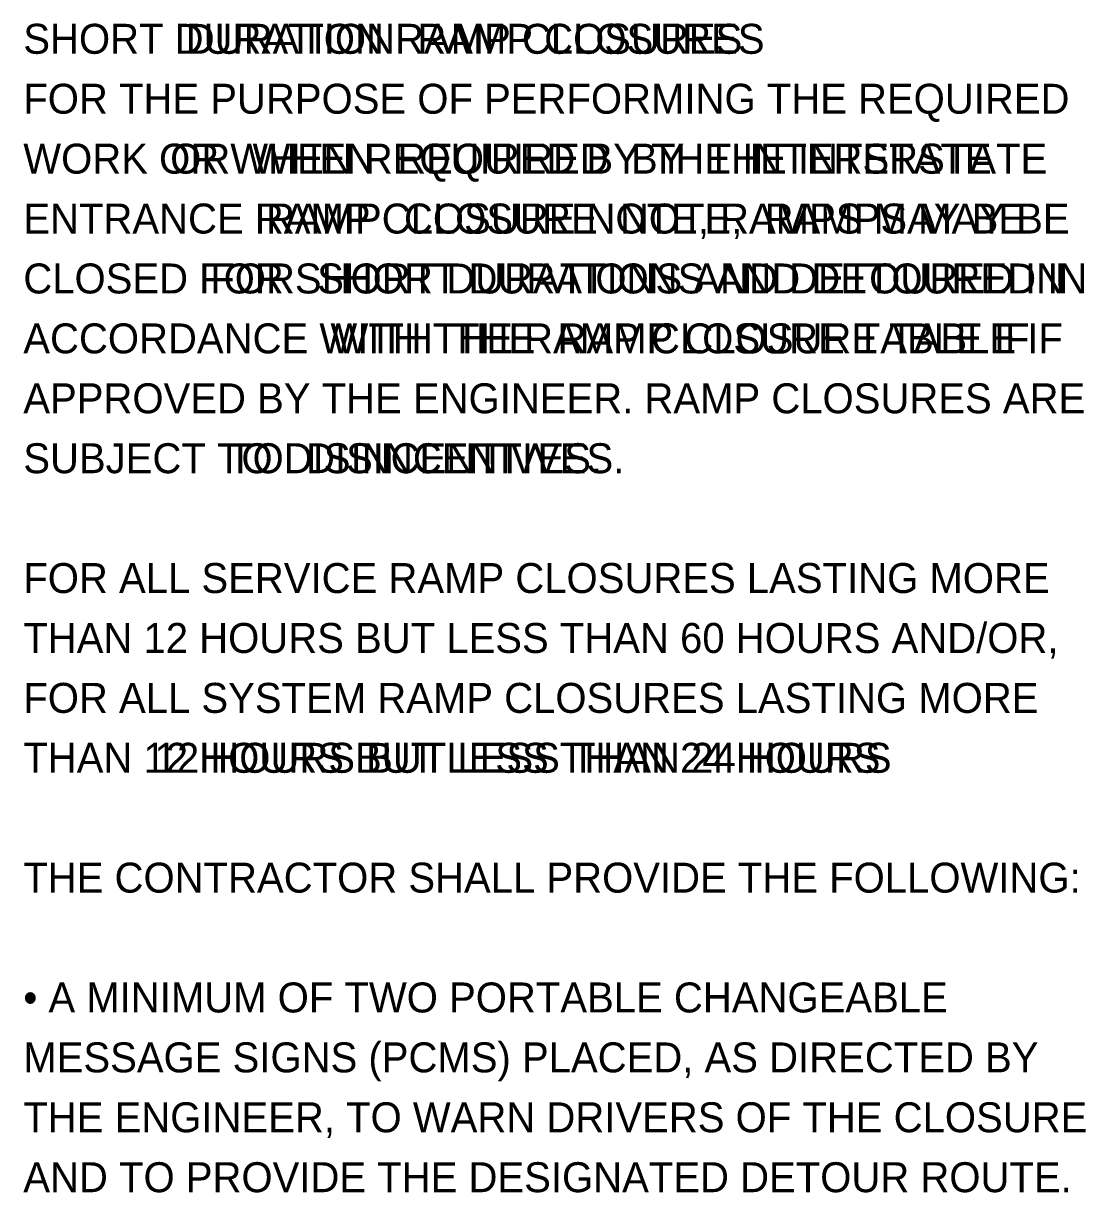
# Model space of a CAD drawing. Extents: x 0 to 37668, y -5 to 18949.
# Drawn here: x 0 to 4.96, y -5.46 to 0 of the extents above; entities that cross this region are included whole.
import ezdxf

# ---------------------------------------------------------------- set-up
doc = ezdxf.new("R2010")
doc.units = 0
doc.layers.add('SH_Text', color=7, linetype='Continuous')

msp = doc.modelspace()

# ---------------------------------------------------------------- texts
at = {"layer": 'SH_Text'}
for s, p in [('SHORT  DURATION  RAMP CLOSURES', (0, -0.14)), ('SHORT  DURATION  RAMP CLOSURES', (0, -0.14)), ('SHORT DURATION RAMP CLOSURES', (0, -0.14)), ('FOR THE PURPOSE OF PERFORMING THE REQUIRED', (0, -0.42)), ('FOR THE PURPOSE OF PERFORMING THE REQUIRED', (0, -0.42)), ('FOR THE PURPOSE OF PERFORMING THE REQUIRED', (0, -0.42)), ('WORK  OR  WHEN  REQUIRED  BY  THE INTERSTATE', (0, -0.7)), ('WORK  OR  WHEN  REQUIRED  BY  THE INTERSTATE', (0, -0.7)), ('WORK OR WHEN REQUIRED BY THE INTERSTATE', (0, -0.7)), ('ENTRANCE  RAMP  CLOSURE  NOTE,  RAMPS MAY BE', (0, -0.98)), ('ENTRANCE  RAMP  CLOSURE  NOTE,  RAMPS MAY BE', (0, -0.98)), ('ENTRANCE RAMP CLOSURE NOTE, RAMPS MAY BE', (0, -0.98)), ('CLOSED  FOR  SHORT DURATIONS AND DETOURED IN', (0, -1.26)), ('CLOSED  FOR  SHORT DURATIONS AND DETOURED IN', (0, -1.26)), ('CLOSED FOR SHORT DURATIONS AND DETOURED IN', (0, -1.26)), ('ACCORDANCE  WITH  THE  RAMP CLOSURE TABLE IF', (0, -1.54)), ('ACCORDANCE  WITH  THE  RAMP CLOSURE TABLE IF', (0, -1.54)), ('ACCORDANCE WITH THE RAMP CLOSURE TABLE IF', (0, -1.54)), ('APPROVED BY THE ENGINEER. RAMP CLOSURES ARE', (0, -1.82)), ('APPROVED BY THE ENGINEER. RAMP CLOSURES ARE', (0, -1.82)), ('APPROVED BY THE ENGINEER. RAMP CLOSURES ARE', (0, -1.82)), ('SUBJECT  TO  DISINCENTIVES.', (0, -2.1)), ('SUBJECT  TO  DISINCENTIVES.', (0, -2.1)), ('SUBJECT TO DISINCENTIVES.', (0, -2.1)), ('FOR ALL SERVICE RAMP CLOSURES LASTING MORE', (0, -2.66)), ('FOR ALL SERVICE RAMP CLOSURES LASTING MORE', (0, -2.66)), ('FOR ALL SERVICE RAMP CLOSURES LASTING MORE', (0, -2.66)), ('THAN 12 HOURS BUT LESS THAN 60 HOURS AND/OR,', (0, -2.94)), ('THAN 12 HOURS BUT LESS THAN 60 HOURS AND/OR,', (0, -2.94)), ('THAN 12 HOURS BUT LESS THAN 60 HOURS AND/OR,', (0, -2.94)), ('FOR ALL SYSTEM RAMP CLOSURES LASTING MORE', (0, -3.22)), ('FOR ALL SYSTEM RAMP CLOSURES LASTING MORE', (0, -3.22)), ('FOR ALL SYSTEM RAMP CLOSURES LASTING MORE', (0, -3.22)), ('THAN  12 HOURS BUT LESS THAN 24 HOURS', (0, -3.5)), ('THAN  12 HOURS BUT LESS THAN 24 HOURS', (0, -3.5)), ('THAN 12 HOURS BUT LESS THAN 24 HOURS', (0, -3.5)), ('THE CONTRACTOR SHALL PROVIDE THE FOLLOWING:', (0, -4.06)), ('THE CONTRACTOR SHALL PROVIDE THE FOLLOWING:', (0, -4.06)), ('THE CONTRACTOR SHALL PROVIDE THE FOLLOWING:', (0, -4.06)), ('• A MINIMUM OF TWO PORTABLE CHANGEABLE', (0, -4.62)), ('• A MINIMUM OF TWO PORTABLE CHANGEABLE', (0, -4.62)), ('• A MINIMUM OF TWO PORTABLE CHANGEABLE', (0, -4.62)), ('MESSAGE SIGNS (PCMS) PLACED, AS DIRECTED BY', (0, -4.9)), ('MESSAGE SIGNS (PCMS) PLACED, AS DIRECTED BY', (0, -4.9)), ('MESSAGE SIGNS (PCMS) PLACED, AS DIRECTED BY', (0, -4.9)), ('THE ENGINEER, TO WARN DRIVERS OF THE CLOSURE', (0, -5.18)), ('THE ENGINEER, TO WARN DRIVERS OF THE CLOSURE', (0, -5.18)), ('THE ENGINEER, TO WARN DRIVERS OF THE CLOSURE', (0, -5.18)), ('AND TO PROVIDE THE DESIGNATED DETOUR ROUTE.', (0, -5.46)), ('AND TO PROVIDE THE DESIGNATED DETOUR ROUTE.', (0, -5.46)), ('AND TO PROVIDE THE DESIGNATED DETOUR ROUTE.', (0, -5.46))]:
    msp.add_text(s, height=0.14, dxfattribs=at).set_placement(p)

doc.saveas('drawing.dxf')
